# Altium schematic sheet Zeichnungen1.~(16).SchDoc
size A4; PageSetup: Record=PageOptions¦CenterHorizontal=True¦CenterVertical=True¦PrintScale=1.00¦XCorrection=1.00¦YCorrection=1.00¦PrintKind=0¦BorderSize=5000000¦LeftOffset=0¦BottomOffset=0¦Orientation=2¦PaperLength=1000¦PaperWidth=1000¦Scale=100¦PaperSource=7¦PrintQuality=-3¦MediaType=1¦DitherType=10¦PrintScaleMode=1¦PaperKind=A4¦PaperIndex=9
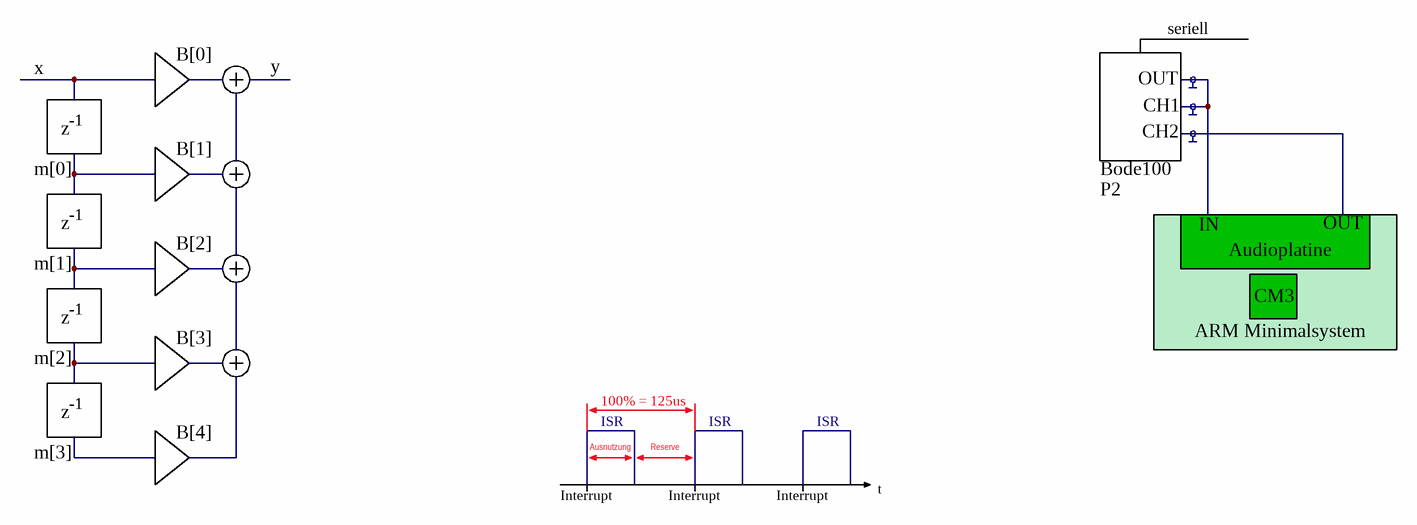
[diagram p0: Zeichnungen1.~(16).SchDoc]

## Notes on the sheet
- x
- B[0]
- y
- seriell
- z
- -1
- OUT
- CH2
- CH1
- m[0]
- B[1]
- Bode100
- P2
- m[1]
- B[2]
- IN
- Audioplatine
- B[3]
- ARM Minimalsystem
- CM3
- m[2]
- 100% = 125us
- m[3]
- B[4]
- Ausnutzung
- ISR
- Reserve
- Interrupt
- t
